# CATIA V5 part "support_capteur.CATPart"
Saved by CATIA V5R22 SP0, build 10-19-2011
Part number: support_capteur_cours
Bounding box of the stored display mesh (mm): x 0 to 5, y -42.5 to 42.5, z -11.5 to 11.5
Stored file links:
  C:\Users\amejo\Downloads\support capteur\support_capteur.CATPart
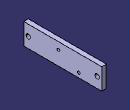
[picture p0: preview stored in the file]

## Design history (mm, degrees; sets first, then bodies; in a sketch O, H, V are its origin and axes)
Body1 (main body)
  Sketch1 on yz-plane, origin (0, 0, 0), H (0, 1, 0), V (0, 0, 1)
    point P1 (-42.5, 11.5)
    line L1 (-42.5, 11.5) -> (42.5, 11.5)
    line L2 (42.5, 11.5) -> (42.5, -11.5)
    line L3 (42.5, -11.5) -> (-42.5, -11.5)
    line L4 (-42.5, -11.5) -> (-42.5, 11.5)
    point P2 (42.5, 11.5)
    point P4 (-42.5, -11.5)
    length L1 = 85
    length L4 = 23
    horizontal: L1 H, L3 H
    vertical: L2 V, L4 V
    symmetry: P1 P2 V, P4 P1 H
  Pad1: profile Sketch1, direction (1, 0, 0), length 5
  Sketch2 on end face of Pad1, origin (5, 0, 0), H (0, 1, 0), V (0, 0, 1)
    circle A1 centre (-37.5, 0) radius 2.5
    point P1 (-37.5, 0)
    reference projected line E1 (-42.5, 6.5) -> (-42.5, -6.5) from edge [face of Pad1 from Sketch1.L4 | end face of Pad1]
    radius A1 = 2.5
    distance P1 E1 = 5
    coincidence: P1 H
  Pocket1: profile Sketch2, direction (-1, 0, 0), through (limit type 3)
  Mirror1: of Pocket1, about zx-plane
  Sketch3 on end face of Pad1, origin (5, 0, 0), H (0, 1, 0), V (0, 0, 1)
    circle A1 centre (-4.7, 3.8) radius 1.5
    point P1 (-4.7, 3.8)
    circle A2 centre (17.5, -6.5) radius 1.5
    point P2 (17.5, -6.5)
    reference projected line E1 (-42.5, 11.5) -> (-42.5, -11.5) from edge [face of Pad1 from Sketch1.L4 | end face of Pad1]
    reference projected line E2 (-42.5, -11.5) -> (42.5, -11.5) from edge [face of Pad1 from Sketch1.L3 | end face of Pad1]
    radius A2 = 1.5
    distance P2 E1 = 60
    distance P2 P1 H = 22.2
    distance P2 P1 V = 10.3
    radius A1 = 1.5
    distance P2 E2 = 5
  Pocket2: profile Sketch3, direction (-1, 0, 0), through (limit type 3)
